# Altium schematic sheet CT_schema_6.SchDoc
size 373 x 245 mm
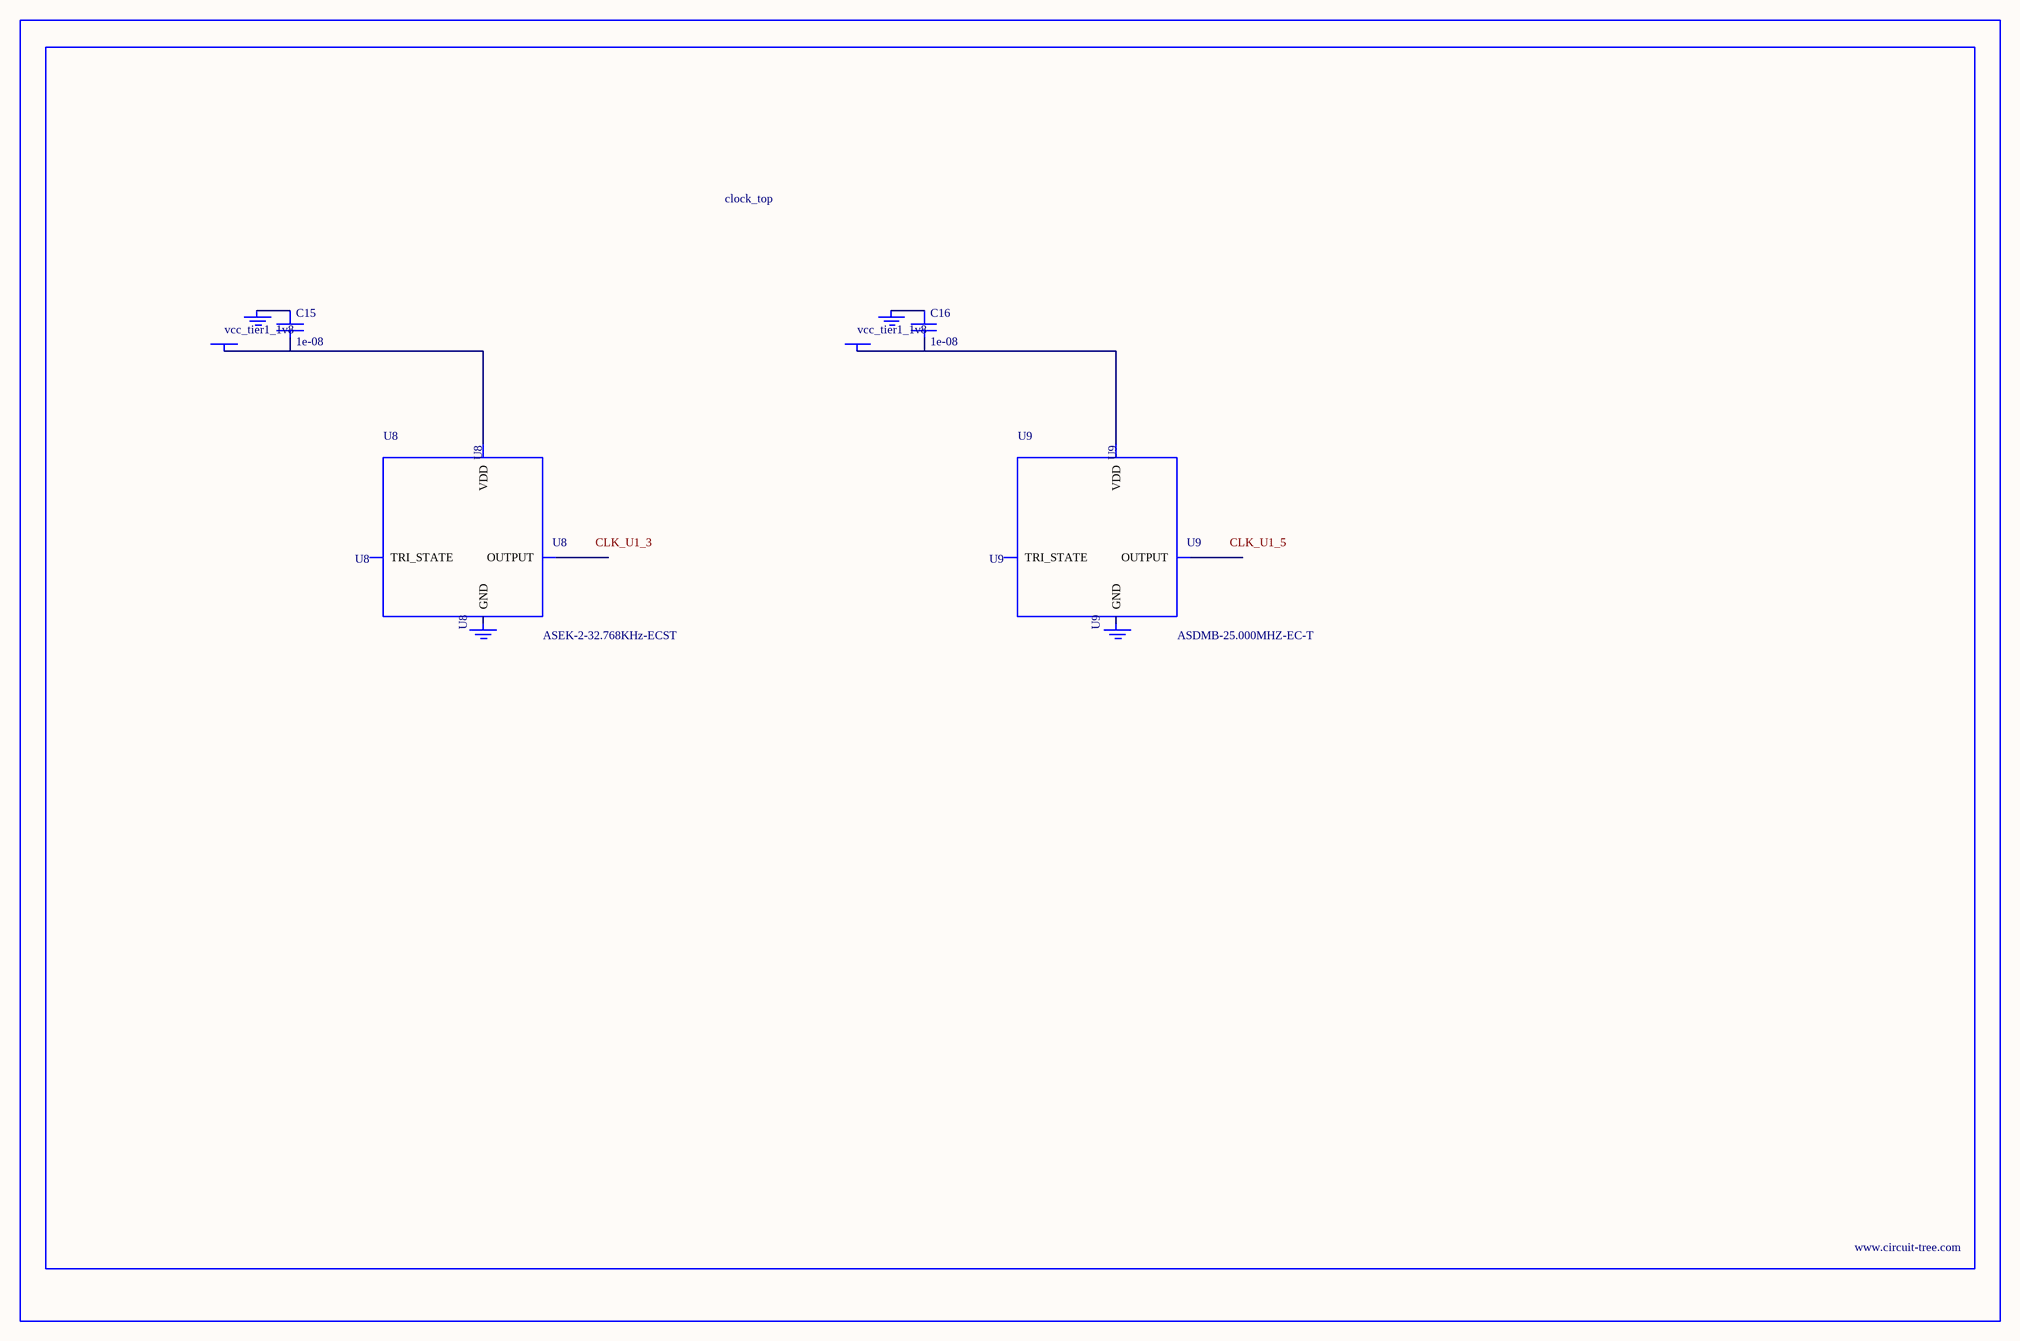
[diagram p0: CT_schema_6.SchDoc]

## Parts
BORDER5  (no value)
C15  1e-08  [C0402]
C16  1e-08  [C0402]
GND_INSTANCE_5_0  (no value)
GND_INSTANCE_5_1  (no value)
GND_INSTANCE_5_2  (no value)
GND_INSTANCE_5_3  (no value)
POWER_INSTANCE_5_0  vcc_tier1_1v8
POWER_INSTANCE_5_1  vcc_tier1_1v8
U8  ASEK-2-32.768KHz-ECST  [ASEK]
U9  ASDMB-25.000MHZ-EC-T  [ASDMB-XX.XXXXMHZ-XX-XX-XXX]

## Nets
NetC15_1: C15.1 GND_INSTANCE_5_0.0(GND)
NetC15_2: C15.2 POWER_INSTANCE_5_0.0(PWR) U8.4(VDD)
NetC16_1: C16.1 GND_INSTANCE_5_2.0(GND)
NetC16_2: C16.2 POWER_INSTANCE_5_1.0(PWR) U9.4(VDD)

Not connected (* = marked no-connect by the designer): GND_INSTANCE_5_1 0(GND); GND_INSTANCE_5_3 0(GND); U8 1(TRI_STATE) 2(GND) 3(OUTPUT); U9 1(TRI_STATE) 2(GND) 3(OUTPUT)

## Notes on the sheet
- Labels drawn without touching a wire or pin: CLK_U1_3, CLK_U1_5

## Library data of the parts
BORDER5 = BORDER_PAGE5
C15 C16 = C0402C103K3RAC
GND_INSTANCE_5_0-GND_INSTANCE_5_3 = GND
POWER_INSTANCE_5_0 POWER_INSTANCE_5_1 = PWR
